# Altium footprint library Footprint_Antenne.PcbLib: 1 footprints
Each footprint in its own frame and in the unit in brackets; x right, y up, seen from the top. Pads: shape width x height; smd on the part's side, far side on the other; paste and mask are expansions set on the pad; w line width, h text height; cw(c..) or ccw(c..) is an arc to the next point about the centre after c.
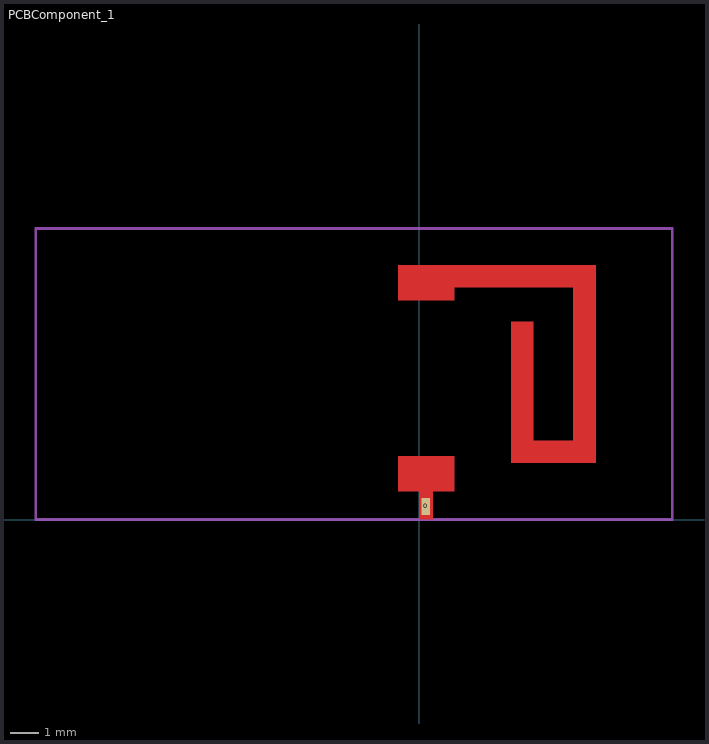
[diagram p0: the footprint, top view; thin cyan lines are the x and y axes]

## PCBComponent_1 [mm]
pads (1):
  rect 0.3x0.6 smd: 0(0.245,0.47)
Top Layer:
  rectangle: 3.25,2 4.05,7
  rectangle: 3.25,2 5.45,2.8
  rectangle: 5.45,2 6.25,9
  rectangle: 1.25,8.2 6.25,9
  rectangle: -0.75,7.75 1.25,9
  rectangle: -0.75,1 1.25,2.25
  rectangle: 0,0 0.5,1
Mechanical 1:
  lines w0.1: -13.55,0 8.95,0 8.95,10.3 -13.55,10.3 -13.55,0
